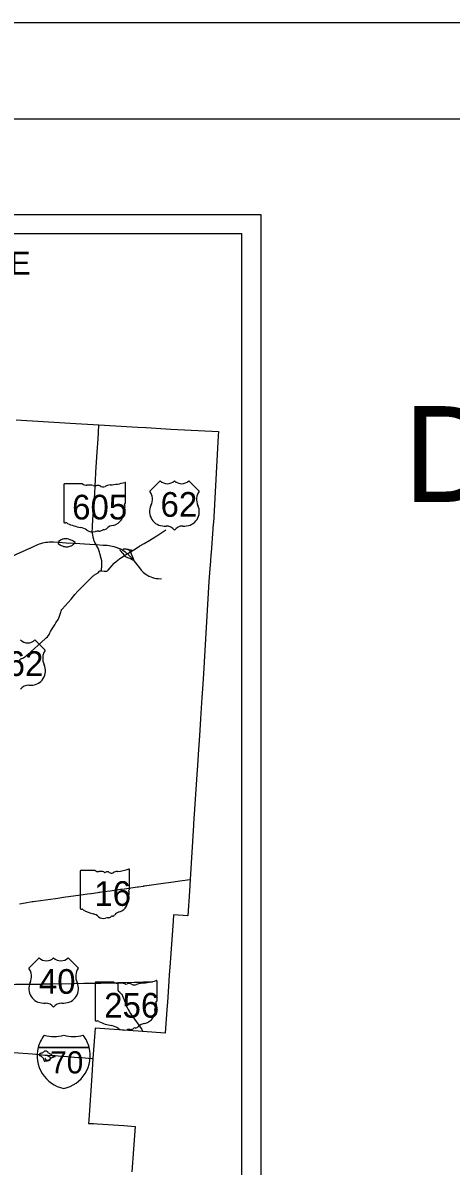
# Model space of a CAD drawing. Extents: x -7.1 to 34, y 0 to 22.
# Drawn here: x 7.76 to 9.99, y 16.03 to 22 of the extents above; entities that cross this region are included whole.
import ezdxf

# ---------------------------------------------------------------- set-up
doc = ezdxf.new("R2010")
doc.units = 0
for name, color, linetype in [('GM_X_County', 7, 'Continuous'), ('GM_X_Interchange_Ramps', 7, 'Continuous'), ('GM_X_Interstate_Route', 7, 'Continuous'), ('GM_X_Interstate_Shield', 7, 'Continuous'), ('GM_X_State_Route', 7, 'Continuous'), ('GM_X_State_Shield', 7, 'Continuous'), ('GM_X_US_Route', 7, 'Continuous'), ('GM_X_US_Shield', 7, 'Continuous'), ('SH_Border', 7, 'Continuous'), ('SH_Cut_Line', 7, 'Continuous'), ('SH_Data', 7, 'Continuous'), ('SH_Text', 7, 'Continuous')]:
    doc.layers.add(name, color=color, linetype=linetype)

msp = doc.modelspace()

# ---------------------------------------------------------------- linework, layer by layer
at = {"layer": 'GM_X_County'}
msp.add_lwpolyline([(7.7234, 19.9275), (8.0063, 19.9111), (8.1554, 19.9022), (8.3292, 19.8922), (8.3589, 19.8902), (8.4004, 19.888), (8.4028, 19.8879), (8.5301, 19.8801), (8.7798, 19.8672), (8.7784, 19.8444), (8.7742, 19.7799), (8.7531, 19.3885), (8.7525, 19.3863), (8.7509, 19.3594), (8.7407, 19.2349), (8.7399, 19.2247), (8.7371, 19.1909), (8.734, 19.1528), (8.7298, 19.0847), (8.7017, 18.6039), (8.7018, 18.6029), (8.6964, 18.5237), (8.6935, 18.4785), (8.6865, 18.3671), (8.6803, 18.2789), (8.6752, 18.2081), (8.67, 18.1263), (8.6655, 18.052), (8.649, 17.8203), (8.6488, 17.8133), (8.6322, 17.5301), (8.6281, 17.4678), (8.6195, 17.3391), (8.5447, 17.3458), (8.5424, 17.3122), (8.5257, 17.0722), (8.5229, 17.0322), (8.5206, 16.9988), (8.5129, 16.8889), (8.5103, 16.8509), (8.5017, 16.7281), (8.3846, 16.7361), (8.1353, 16.7531), (8.1247, 16.5954), (8.1187, 16.5065), (8.1026, 16.2742), (8.1014, 16.2562), (8.1281, 16.2557), (8.1476, 16.2545), (8.2864, 16.2449), (8.3452, 16.241), (8.3276, 16.0031)], dxfattribs=at)
at = {"layer": 'GM_X_Interchange_Ramps'}
for points in [[(7.9429, 19.2894), (7.9427, 19.2823), (7.955, 19.2746), (7.9593, 19.2723), (7.9637, 19.2703), (7.9683, 19.2688), (7.9717, 19.2681), (7.976, 19.267), (7.9816, 19.2661), (7.984, 19.2661)], [(7.9865, 19.3069), (7.9831, 19.307), (7.9756, 19.3069), (7.9721, 19.3066), (7.968, 19.3056), (7.9654, 19.3047), (7.9595, 19.3019), (7.954, 19.2994), (7.9498, 19.2974), (7.947, 19.2964), (7.947, 19.2891)], [(7.984, 19.2661), (7.9868, 19.2662), (7.9934, 19.2663), (7.9993, 19.2669), (8.0052, 19.2687), (8.0102, 19.2708), (8.0138, 19.2727), (8.0176, 19.2751), (8.0217, 19.2773), (8.0255, 19.2793), (8.0257, 19.2842)], [(8.0317, 19.2839), (8.0319, 19.2888), (8.0223, 19.2947), (8.0159, 19.298), (8.0104, 19.3006), (8.0056, 19.3026), (8.0012, 19.3042), (7.9982, 19.305), (7.9897, 19.3065), (7.9865, 19.3069)], [(8.2679, 19.2543), (8.2651, 19.2486), (8.2671, 19.246), (8.2713, 19.2408), (8.2757, 19.2358), (8.2792, 19.2321), (8.2877, 19.2229), (8.2893, 19.2203)], [(8.3296, 19.2451), (8.3284, 19.2471), (8.3231, 19.2474), (8.3201, 19.2478), (8.3174, 19.2485), (8.314, 19.2494), (8.3094, 19.2509), (8.3054, 19.2518), (8.3017, 19.2524), (8.2979, 19.2529), (8.2943, 19.2532), (8.2827, 19.2534), (8.2796, 19.2478)], [(8.2893, 19.2203), (8.2906, 19.2185), (8.2931, 19.2167), (8.2971, 19.2138), (8.3011, 19.2115), (8.3053, 19.2096), (8.3153, 19.2059), (8.32, 19.2038), (8.3251, 19.2005), (8.3301, 19.1963), (8.3326, 19.1989)], [(8.3208, 19.2396), (8.3187, 19.2429), (8.3159, 19.2452), (8.3128, 19.2474), (8.3083, 19.2495), (8.3094, 19.2509)], [(8.3354, 19.1955), (8.3385, 19.198), (8.3362, 19.203), (8.3264, 19.2281), (8.3247, 19.2322), (8.3217, 19.238), (8.3208, 19.2396)], [(7.8437, 16.6166), (7.8433, 16.6123), (7.8462, 16.6114), (7.8482, 16.6106), (7.8502, 16.6097), (7.852, 16.6087), (7.8539, 16.6075), (7.8557, 16.6062), (7.8575, 16.6047), (7.8594, 16.603), (7.8609, 16.6014), (7.8625, 16.5996), (7.8642, 16.5972), (7.8657, 16.5947), (7.8668, 16.5924), (7.868, 16.5896), (7.8688, 16.587), (7.8695, 16.5842), (7.8703, 16.5809), (7.8732, 16.5807)], [(7.8771, 16.6333), (7.875, 16.6336), (7.8735, 16.6336), (7.8722, 16.6333), (7.8703, 16.6323), (7.8662, 16.6288), (7.8627, 16.6261), (7.8606, 16.6248), (7.858, 16.6236), (7.8547, 16.6223), (7.8513, 16.6214), (7.8486, 16.6207), (7.8463, 16.6204), (7.8459, 16.6165)], [(7.8734, 16.5834), (7.8756, 16.5833), (7.8814, 16.5828), (7.8857, 16.5825), (7.8874, 16.5824), (7.8942, 16.5841), (7.9013, 16.5898), (7.9037, 16.594), (7.9055, 16.5959), (7.9072, 16.5975), (7.9091, 16.599), (7.9117, 16.6007), (7.9141, 16.602), (7.9162, 16.603), (7.9184, 16.6038), (7.9209, 16.6045), (7.9232, 16.605), (7.9249, 16.6053), (7.9272, 16.6056), (7.9276, 16.6103)], [(7.8877, 16.6127), (7.8876, 16.6089), (7.8922, 16.6081), (7.8937, 16.6076), (7.895, 16.607), (7.8962, 16.6063), (7.8973, 16.6055), (7.8984, 16.6044), (7.8993, 16.6034), (7.9002, 16.602), (7.9008, 16.6008), (7.9013, 16.5992), (7.9015, 16.5977), (7.9015, 16.596), (7.9012, 16.5941), (7.9003, 16.5918), (7.8993, 16.5902), (7.898, 16.5889), (7.8963, 16.5877), (7.8944, 16.5866), (7.8925, 16.5858), (7.8907, 16.5852), (7.8884, 16.5848), (7.8862, 16.5849), (7.8846, 16.5852), (7.8821, 16.5863), (7.8807, 16.5873), (7.8794, 16.5885), (7.8783, 16.5899), (7.8777, 16.591), (7.8771, 16.5924), (7.8762, 16.5956), (7.8744, 16.5957)], [(7.9103, 16.6117), (7.9106, 16.616), (7.9057, 16.6169), (7.9027, 16.6178), (7.9004, 16.6189), (7.8976, 16.6205), (7.895, 16.6223), (7.8916, 16.625), (7.8888, 16.6275), (7.8846, 16.6313), (7.8828, 16.6326), (7.8814, 16.6333), (7.8799, 16.6339), (7.8791, 16.6338), (7.8783, 16.6334), (7.8771, 16.6333)]]:
    msp.add_lwpolyline(points, dxfattribs=at)
at = {"layer": 'GM_X_Interstate_Route'}
for points in [[(7.6632, 16.6307), (7.7102, 16.6268), (7.8097, 16.6198), (7.8437, 16.6166), (7.8459, 16.6165), (7.8758, 16.6135), (7.8877, 16.6127)], [(7.8877, 16.6127), (7.9103, 16.6117), (7.9276, 16.6103), (7.9594, 16.6077), (7.9596, 16.6077)], [(7.9596, 16.6077), (7.9919, 16.605), (8.0468, 16.6013), (8.0483, 16.6012)], [(8.0483, 16.6012), (8.066, 16.6), (8.118, 16.5959), (8.1247, 16.5954)]]:
    msp.add_lwpolyline(points, dxfattribs=at)
at = {"layer": 'GM_X_Interstate_Shield'}
for p, q in [((7.8386, 16.6519), (8.1057, 16.6519)), ((8.1057, 16.6519), (7.8386, 16.6519)), ((8.1057, 16.6519), (7.8386, 16.6519))]:
    msp.add_line(p, q, dxfattribs=at)
for centre, start, end in [((8.0068, 16.6094), 141.66896, 165.80665), ((7.9214, 16.8829), 253.00908, 286.99093), ((8.0229, 16.8829), 253.00908, 286.99093), ((7.9374, 16.6094), 14.19335, 38.33104), ((8.0068, 16.6094), 165.80665, 258.46304), ((7.9374, 16.6094), 281.53696, 14.19335)]:
    msp.add_arc(centre, 0.1735, start, end, dxfattribs=at)
at = {"layer": 'GM_X_State_Route'}
for points in [[(8.1356, 19.5797), (8.1372, 19.6165), (8.1392, 19.6478), (8.1396, 19.6544), (8.147, 19.7597), (8.1514, 19.8295), (8.1535, 19.8621), (8.1554, 19.9022)], [(8.1339, 19.548), (8.1341, 19.5505), (8.1355, 19.5758), (8.1356, 19.5797)], [(8.1241, 19.3981), (8.1247, 19.411), (8.1258, 19.4274), (8.1306, 19.4999), (8.1319, 19.5191), (8.1339, 19.548)], [(8.1229, 19.3817), (8.1241, 19.3981)], [(8.1409, 19.277), (8.1377, 19.2829), (8.1347, 19.2887), (8.1314, 19.296), (8.1296, 19.301), (8.1288, 19.3036), (8.1263, 19.3137), (8.1255, 19.3167), (8.1216, 19.3378), (8.1212, 19.3407), (8.121, 19.3449), (8.1211, 19.3506), (8.1216, 19.3582)], [(8.1216, 19.3582), (8.122, 19.3655), (8.1229, 19.3811), (8.1229, 19.3817)], [(7.7966, 19.2593), (7.8135, 19.2673), (7.8304, 19.2751), (7.8377, 19.2782), (7.8463, 19.2814), (7.8534, 19.2836), (7.8631, 19.2862), (7.8695, 19.2878), (7.8779, 19.2893), (7.8874, 19.2906), (7.8956, 19.2913), (7.9052, 19.2915), (7.919, 19.2909), (7.9429, 19.2894), (7.947, 19.2891), (7.9853, 19.2866), (8.0257, 19.2842), (8.0317, 19.2839), (8.0802, 19.2807)], [(8.0802, 19.2807), (8.0811, 19.2806), (8.136, 19.2773)], [(8.136, 19.2773), (8.1409, 19.277), (8.1773, 19.2748), (8.1991, 19.2734), (8.2096, 19.2723), (8.2155, 19.2714), (8.2242, 19.2697), (8.2327, 19.2676), (8.2441, 19.2642), (8.2586, 19.2588), (8.2679, 19.2543), (8.2796, 19.2478), (8.2903, 19.2406), (8.2963, 19.2362), (8.3009, 19.2324)], [(8.1607, 19.2311), (8.1588, 19.2384), (8.1574, 19.2425), (8.1552, 19.2478), (8.1511, 19.258), (8.1455, 19.2686), (8.1409, 19.277)], [(7.5817, 19.1595), (7.5872, 19.162), (7.6317, 19.1826), (7.6353, 19.1843), (7.6729, 19.2018), (7.7294, 19.2283), (7.7406, 19.2334), (7.7768, 19.2502), (7.7946, 19.2584), (7.7966, 19.2593)], [(8.1713, 19.1899), (8.1711, 19.1931), (8.1678, 19.2042), (8.1607, 19.2311)], [(8.3009, 19.2324), (8.3046, 19.2294), (8.31, 19.2244), (8.3142, 19.22), (8.3173, 19.2171), (8.3249, 19.2087), (8.3326, 19.1989), (8.3354, 19.1955), (8.3389, 19.1912), (8.3671, 19.1559), (8.3765, 19.1441), (8.382, 19.1383), (8.3873, 19.1334), (8.3972, 19.1253), (8.4049, 19.1198), (8.4162, 19.1132)], [(8.1697, 19.1398), (8.1698, 19.154), (8.1701, 19.1599)], [(8.1701, 19.1599), (8.1707, 19.1707), (8.1717, 19.1862), (8.1713, 19.1899)], [(8.4162, 19.1132), (8.4185, 19.1123)], [(8.4185, 19.1123), (8.4268, 19.1086), (8.4352, 19.1055), (8.4459, 19.1024), (8.4543, 19.1008), (8.4649, 19.0997), (8.4821, 19.0984)], [(8.2773, 17.4796), (8.3575, 17.4908), (8.3599, 17.4911), (8.3619, 17.4914)], [(8.3619, 17.4914), (8.3889, 17.4954), (8.3909, 17.4957)], [(8.3909, 17.4957), (8.3933, 17.4961), (8.4793, 17.5081), (8.5456, 17.5177), (8.5782, 17.5221), (8.6322, 17.5301)], [(7.8128, 17.4145), (7.851, 17.4198), (7.9294, 17.4309), (7.9416, 17.4326), (7.9702, 17.4367), (8.0606, 17.4495), (8.0961, 17.4544), (8.1138, 17.457), (8.1154, 17.4572)], [(8.1154, 17.4572), (8.15, 17.4621), (8.1516, 17.4623)], [(8.1516, 17.4623), (8.1562, 17.4629), (8.1603, 17.4635), (8.1818, 17.4665), (8.2145, 17.4708)], [(8.2145, 17.4708), (8.2255, 17.4722), (8.2479, 17.4755), (8.2677, 17.4783)], [(8.2677, 17.4783), (8.2686, 17.4784), (8.2773, 17.4796)], [(7.741, 17.4028), (7.7706, 17.4085), (7.8081, 17.4138), (7.8128, 17.4145)], [(8.2536, 16.9912), (8.2538, 16.9826), (8.2539, 16.979)], [(8.2539, 16.979), (8.2543, 16.9695), (8.2547, 16.9591), (8.2549, 16.9528), (8.2552, 16.9512), (8.2558, 16.9501)], [(8.2558, 16.9501), (8.256, 16.9497), (8.2565, 16.9491), (8.2642, 16.9413)], [(8.2642, 16.9413), (8.2672, 16.9383), (8.2717, 16.9336), (8.2748, 16.9302), (8.2767, 16.9263), (8.2785, 16.9221)], [(8.2785, 16.9221), (8.2804, 16.9176), (8.2822, 16.9131)], [(8.2822, 16.9131), (8.2824, 16.9126), (8.285, 16.9064), (8.2897, 16.8956), (8.3037, 16.8605), (8.3059, 16.8554), (8.3082, 16.8513), (8.3137, 16.8422)], [(8.3137, 16.8422), (8.3212, 16.8297)], [(8.3212, 16.8297), (8.3243, 16.8256), (8.342, 16.7999), (8.3644, 16.7685), (8.3791, 16.746), (8.3846, 16.7361)]]:
    msp.add_lwpolyline(points, dxfattribs=at)
at = {"layer": 'GM_X_State_Shield'}
for p, q in [((7.9726, 19.5902), (7.9726, 19.3946)), ((8.0701, 19.5936), (7.9758, 19.5936)), ((8.2947, 19.4961), (8.2947, 19.5984)), ((8.2947, 19.4962), (8.2947, 19.4961)), ((8.0583, 17.5735), (8.0583, 17.3779)), ((8.1363, 17.5768), (8.0608, 17.5768)), ((8.3159, 17.4794), (8.3159, 17.5817)), ((8.3159, 17.4794), (8.3159, 17.4794)), ((8.1367, 16.9903), (8.1367, 16.7947)), ((8.2342, 16.9937), (8.1399, 16.9937)), ((8.4588, 16.8962), (8.4588, 16.9985)), ((8.4588, 16.8962), (8.4588, 16.8962))]:
    msp.add_line(p, q, dxfattribs=at)
for centre, radius, start, end in [((8.0612, 17.5739), 0.00299, 98.1301, 188.1301), ((8.1542, 17.5995), 0.029, 231.61951, 271.11188), ((8.1638, 17.467), 0.104, 80.48669, 94.98827), ((8.1874, 17.5749), 0.00835, 219.79206, 297.10237), ((8.1997, 17.5523), 0.0174, 54.46668, 119.14113), ((8.2221, 17.5833), 0.0209, 233.85621, 294.82819), ((8.259, 17.5171), 0.055, 97.34618, 120.76885), ((8.2242, 17.8435), 0.2733, 275.84447, 288.90645), ((8.3131, 17.5821), 0.00287, 351.86209, 97.738), ((8.2395, 17.4235), 0.0684, 292.30889, 8.98584), ((8.3262, 17.4365), 0.0194, 136.8065, 186.92959), ((8.3153, 17.4718), 0.00444, 107.94398, 210.33697), ((8.287, 17.4589), 0.0267, 340.03296, 23.64957), ((8.3129, 17.479), 0.00307, 289.60381, 7.73413), ((8.0612, 17.3774), 0.00301, 171.95839, 258.30661), ((8.0617, 17.3975), 0.023, 267.33899, 280.60386), ((8.0664, 17.3666), 0.00829, 29.74838, 93.27175), ((8.171, 17.5423), 0.1973, 240.41292, 257.1985), ((8.1122, 17.29), 0.0617, 47.18416, 75.83597), ((8.179, 17.3656), 0.0392, 230.70037, 286.29184), ((8.2016, 17.298), 0.0322, 85.69512, 111.20995), ((8.2045, 17.351), 0.0209, 268.77702, 315.54927), ((8.2234, 17.332), 0.00588, 65.75173, 132.64842), ((8.2209, 17.3589), 0.0221, 282.87319, 323.27711), ((8.2683, 17.323), 0.0374, 94.40312, 142.57675)]:
    msp.add_arc(centre, radius, start, end, dxfattribs=at)
for centre, major_axis, start_param, end_param in [((7.9763, 19.5907), (0.00373, 0), 1.712693, 3.28349), ((8.0926, 19.6163), (0.0362, 0), 4.042523, 4.731795), ((8.1046, 19.4838), (0.1299, 0), 1.404758, 1.657858), ((8.1341, 19.5917), (0.0104, 0), 3.836095, 5.185415), ((8.1494, 19.5691), (0.0217, 0), 0.950623, 2.079405), ((8.1774, 19.6001), (0.0261, 0), 4.081561, 5.145723), ((8.2235, 19.5339), (0.0687, 0), 1.699011, 2.107814), ((8.18, 19.8602), (0.3416, 0), 4.814394, 5.042369), ((8.2911, 19.5989), (0.00359, 0), 6.141152, 7.989035), ((8.1991, 19.4403), (0.0854, 0), 5.101752, 6.440018), ((8.3076, 19.4533), (0.0242, 0), 2.387724, 3.262537), ((8.2939, 19.4886), (0.00555, 0), 1.883978, 3.671073), ((8.2586, 19.4757), (0.0333, 0), 5.934695, 6.695948), ((8.2909, 19.4957), (0.00384, 0), 5.05454, 6.418171), ((7.9763, 19.3942), (0.00376, 0), 3.00124, 4.508301), ((7.9769, 19.4142), (0.0287, 0), 4.665946, 4.897461), ((7.9828, 19.3834), (0.0104, 0), 0.519207, 1.627899), ((8.1136, 19.5591), (0.2467, 0), 4.195997, 4.488961), ((8.04, 19.3068), (0.0772, 0), 0.823519, 1.323587), ((8.1235, 19.3824), (0.049, 0), 4.026481, 4.996735), ((8.1518, 19.3148), (0.0402, 0), 1.495662, 1.94098), ((8.1554, 19.3677), (0.0261, 0), 4.691044, 5.507374), ((8.179, 19.3488), (0.00735, 0), 1.147584, 2.315152), ((8.1758, 19.3757), (0.0276, 0), 4.937069, 5.64225), ((8.2351, 19.3397), (0.0468, 0), 1.647645, 2.488434), ((8.1404, 16.9907), (0.00373, 0), 1.712693, 3.28349), ((8.2567, 17.0164), (0.0362, 0), 4.042523, 4.731795), ((8.2687, 16.8839), (0.1299, 0), 1.404758, 1.657858), ((8.2982, 16.9917), (0.0104, 0), 3.836095, 5.185415), ((8.3135, 16.9691), (0.0217, 0), 0.950623, 2.079405), ((8.3415, 17.0001), (0.0261, 0), 4.081561, 5.145723), ((8.3877, 16.9339), (0.0687, 0), 1.699011, 2.107814), ((8.3441, 17.2603), (0.3416, 0), 4.814394, 5.042369), ((8.4552, 16.999), (0.00359, 0), 6.141152, 7.989035), ((8.458, 16.8887), (0.00555, 0), 1.883978, 3.671073), ((8.4227, 16.8758), (0.0333, 0), 5.934695, 6.695948), ((8.455, 16.8958), (0.00384, 0), 5.05454, 6.418171), ((8.3632, 16.8404), (0.0854, 0), 5.101752, 6.440018), ((8.4717, 16.8534), (0.0242, 0), 2.387724, 3.262537), ((8.1404, 16.7943), (0.00376, 0), 3.00124, 4.508301), ((8.141, 16.8143), (0.0287, 0), 4.665946, 4.897461), ((8.1469, 16.7834), (0.0104, 0), 0.519207, 1.627899), ((8.2777, 16.9592), (0.2467, 0), 4.195997, 4.488961), ((8.2041, 16.7069), (0.0772, 0), 0.823519, 1.323587), ((8.3992, 16.7398), (0.0468, 0), 1.647645, 2.488434), ((8.2876, 16.7825), (0.049, 0), 4.026481, 4.996735), ((8.3159, 16.7149), (0.0402, 0), 1.495662, 1.94098), ((8.3195, 16.7678), (0.0261, 0), 4.691044, 5.507374), ((8.3431, 16.7489), (0.00735, 0), 1.147584, 2.315152), ((8.34, 16.7758), (0.0276, 0), 4.937069, 5.64225)]:
    msp.add_ellipse(centre, major_axis=major_axis, ratio=0.8, start_param=start_param, end_param=end_param, dxfattribs=at)
at = {"layer": 'GM_X_US_Route'}
for points in [[(8.4215, 19.3009), (8.4347, 19.3086), (8.4584, 19.3237), (8.495, 19.3471), (8.505, 19.3534)], [(8.3699, 19.27), (8.3922, 19.2838), (8.4215, 19.3009)], [(8.2612, 19.2017), (8.2654, 19.205), (8.2728, 19.2101), (8.2819, 19.2157), (8.2893, 19.2203), (8.3046, 19.2294), (8.3119, 19.234)], [(8.3119, 19.234), (8.3208, 19.2396), (8.3296, 19.2451), (8.3463, 19.2556), (8.3477, 19.2564)], [(8.3477, 19.2564), (8.3618, 19.265)], [(8.3618, 19.265), (8.3678, 19.2688), (8.3699, 19.27)], [(8.2037, 19.144), (8.2147, 19.1567)], [(8.2147, 19.1567), (8.2224, 19.1656), (8.2355, 19.1801)], [(8.2355, 19.1801), (8.2375, 19.1822), (8.2432, 19.1878), (8.256, 19.1976), (8.2612, 19.2017)], [(7.8954, 18.8077), (7.8994, 18.8164), (7.9026, 18.8241), (7.9109, 18.838), (7.9249, 18.8591), (7.9313, 18.869), (7.9429, 18.8865), (7.9467, 18.8936), (7.9488, 18.898), (7.9541, 18.9149), (7.9567, 18.9249), (7.9585, 18.9307), (7.96, 18.9339), (7.9611, 18.9359), (7.9642, 18.941), (8.0104, 18.9928), (8.0302, 19.0165), (8.0461, 19.0342), (8.0524, 19.0408), (8.0624, 19.0511), (8.0784, 19.0676), (8.0922, 19.0814), (8.1041, 19.0935), (8.1077, 19.0969)], [(8.1077, 19.0969), (8.1254, 19.1139), (8.1284, 19.1159), (8.1332, 19.1192), (8.1447, 19.1263), (8.152, 19.1307)], [(8.152, 19.1307), (8.1585, 19.1385), (8.1592, 19.1392), (8.1598, 19.1397), (8.1608, 19.1402), (8.1639, 19.1402), (8.1697, 19.1398), (8.1824, 19.1392), (8.1943, 19.1385), (8.1975, 19.1386), (8.1997, 19.1398), (8.2027, 19.1428), (8.2037, 19.144)], [(7.7961, 18.7144), (7.7996, 18.7177), (7.8205, 18.7366), (7.8523, 18.7652), (7.8809, 18.7908), (7.8866, 18.796), (7.8922, 18.8029), (7.8953, 18.8073), (7.8954, 18.8077)], [(7.7417, 18.6712), (7.7446, 18.6762), (7.7455, 18.6776), (7.7467, 18.679), (7.7482, 18.6805), (7.7496, 18.6814), (7.752, 18.6825), (7.7581, 18.6851), (7.7644, 18.6881)], [(7.7644, 18.6881), (7.7656, 18.6886), (7.7687, 18.6903)], [(7.7687, 18.6903), (7.7697, 18.6909), (7.7729, 18.6935), (7.7786, 18.698), (7.7961, 18.7144)], [(7.7003, 16.9823), (7.7046, 16.9823), (7.7197, 16.9825), (7.7262, 16.9826), (7.7369, 16.9828), (7.7534, 16.983), (7.7706, 16.9832)], [(7.7706, 16.9832), (7.7771, 16.9832), (7.7907, 16.983), (7.792, 16.983)], [(7.792, 16.983), (7.8379, 16.9838), (7.8391, 16.9839)], [(7.8391, 16.9839), (7.848, 16.984), (7.849, 16.984)], [(7.849, 16.984), (7.8589, 16.9843)], [(7.8589, 16.9843), (7.8639, 16.9844)], [(7.8639, 16.9844), (7.868, 16.9846), (7.8688, 16.9846)], [(7.8688, 16.9846), (7.8757, 16.9847), (7.8788, 16.9847)], [(7.8788, 16.9847), (7.9021, 16.9846), (7.9035, 16.9845), (8.013, 16.9866), (8.0277, 16.9868), (8.0778, 16.9877), (8.1193, 16.9879), (8.1195, 16.9879), (8.1651, 16.9888), (8.186, 16.9893), (8.203, 16.9896), (8.2172, 16.9899), (8.219, 16.99)], [(8.219, 16.99), (8.2287, 16.9904)], [(8.2287, 16.9904), (8.2343, 16.9907), (8.2408, 16.991), (8.2536, 16.9912), (8.274, 16.9918), (8.2937, 16.9922), (8.3388, 16.9932), (8.3594, 16.9937), (8.3712, 16.9942)], [(8.3712, 16.9942), (8.3723, 16.9942), (8.3737, 16.9943)], [(8.3737, 16.9943), (8.3886, 16.9949)], [(8.3886, 16.9949), (8.3986, 16.9953)], [(8.3986, 16.9953), (8.3995, 16.9954), (8.4312, 16.9958), (8.435, 16.9959), (8.4359, 16.9959)]]:
    msp.add_lwpolyline(points, dxfattribs=at)
at = {"layer": 'GM_X_US_Shield'}
for p, q in [((8.4748, 19.6103), (8.4211, 19.5566)), ((8.6788, 19.5566), (8.6251, 19.6103)), ((8.4962, 19.3741), (8.507, 19.3741)), ((8.5929, 19.3741), (8.6036, 19.3741)), ((7.8758, 18.726), (7.8221, 18.7797)), ((7.7899, 18.5435), (7.8006, 18.5435)), ((7.8443, 17.1208), (7.7906, 17.0671)), ((8.0483, 17.0671), (7.9946, 17.1208)), ((7.8657, 16.8846), (7.8765, 16.8846)), ((7.9624, 16.8846), (7.9731, 16.8846))]:
    msp.add_line(p, q, dxfattribs=at)
for centre, radius, start, end in [((8.5124, 19.6486), 0.0537, 225.573, 314.427), ((8.5875, 19.6486), 0.0537, 225.573, 314.427), ((8.3595, 19.5135), 0.0752, 334.54712, 35.00093), ((8.7404, 19.5135), 0.0752, 144.99907, 205.45288), ((8.4954, 19.4492), 0.0752, 154.83192, 270.63826), ((8.6045, 19.4492), 0.0752, 269.36174, 25.16808), ((8.507, 19.3204), 0.0537, 36.8699, 90), ((8.5929, 19.3204), 0.0537, 90, 143.1301), ((7.7845, 18.818), 0.0537, 225.573, 314.427), ((7.9373, 18.6829), 0.0752, 144.99907, 205.45288), ((7.8014, 18.6186), 0.0752, 269.36174, 25.16808), ((7.7899, 18.4898), 0.0537, 90, 143.1301), ((7.729, 17.024), 0.0752, 334.54712, 35.00093), ((7.8819, 17.1591), 0.0537, 225.573, 314.427), ((7.957, 17.1591), 0.0537, 225.573, 314.427), ((8.1098, 17.024), 0.0752, 144.99907, 205.45288), ((7.8649, 16.9597), 0.0752, 154.83192, 270.63826), ((7.974, 16.9597), 0.0752, 269.36174, 25.16808), ((7.8765, 16.8309), 0.0537, 36.8699, 90), ((7.9624, 16.8309), 0.0537, 90, 143.1301)]:
    msp.add_arc(centre, radius, start, end, dxfattribs=at)
at = {"layer": 'SH_Border'}
msp.add_lwpolyline([(1.5, 21.5), (33.5, 21.5), (33.5, 0.5), (1.5, 0.5)], close=True, dxfattribs=at)
at = {"layer": 'SH_Cut_Line'}
msp.add_lwpolyline([(0, 0), (34, 0), (34, 22), (0, 22)], close=True, dxfattribs=at)
at = {"layer": 'SH_Data'}
for p, q in [((2, 21), (9, 21)), ((9, 21), (9, 14)), ((2.1, 20.9), (8.9, 20.9)), ((8.9, 20.9), (8.9, 14.1))]:
    msp.add_line(p, q, dxfattribs=at)

# ---------------------------------------------------------------- texts
at = {"layer": 'GM_X_Interstate_Shield'}
msp.add_text('70', height=0.11569, dxfattribs=at).set_placement((7.9016, 16.5174))
at = {"layer": 'GM_X_State_Shield'}
for s, p in [('605', (8.0159, 19.4084)), ('16', (8.1317, 17.3917)), ('256', (8.1832, 16.8085))]:
    msp.add_text(s, height=0.12885, dxfattribs=at).set_placement(p)
at = {"layer": 'GM_X_US_Shield'}
for s, p in [('62', (8.477, 19.4224)), ('62', (7.674, 18.5918)), ('40', (7.842, 16.9329))]:
    msp.add_text(s, height=0.12885, dxfattribs=at).set_placement(p)
at = {"layer": 'SH_Data'}
msp.add_text('FOR SPECIFIC LOCATIONS SEE', height=0.12, dxfattribs=at).set_placement((5.338, 20.6859))
at = {"layer": 'SH_Text'}
msp.add_text('DEPARTMENT OF TRANSPORTATION', height=0.5, dxfattribs=at).set_placement((9.7466, 19.5))

doc.saveas('drawing.dxf')
